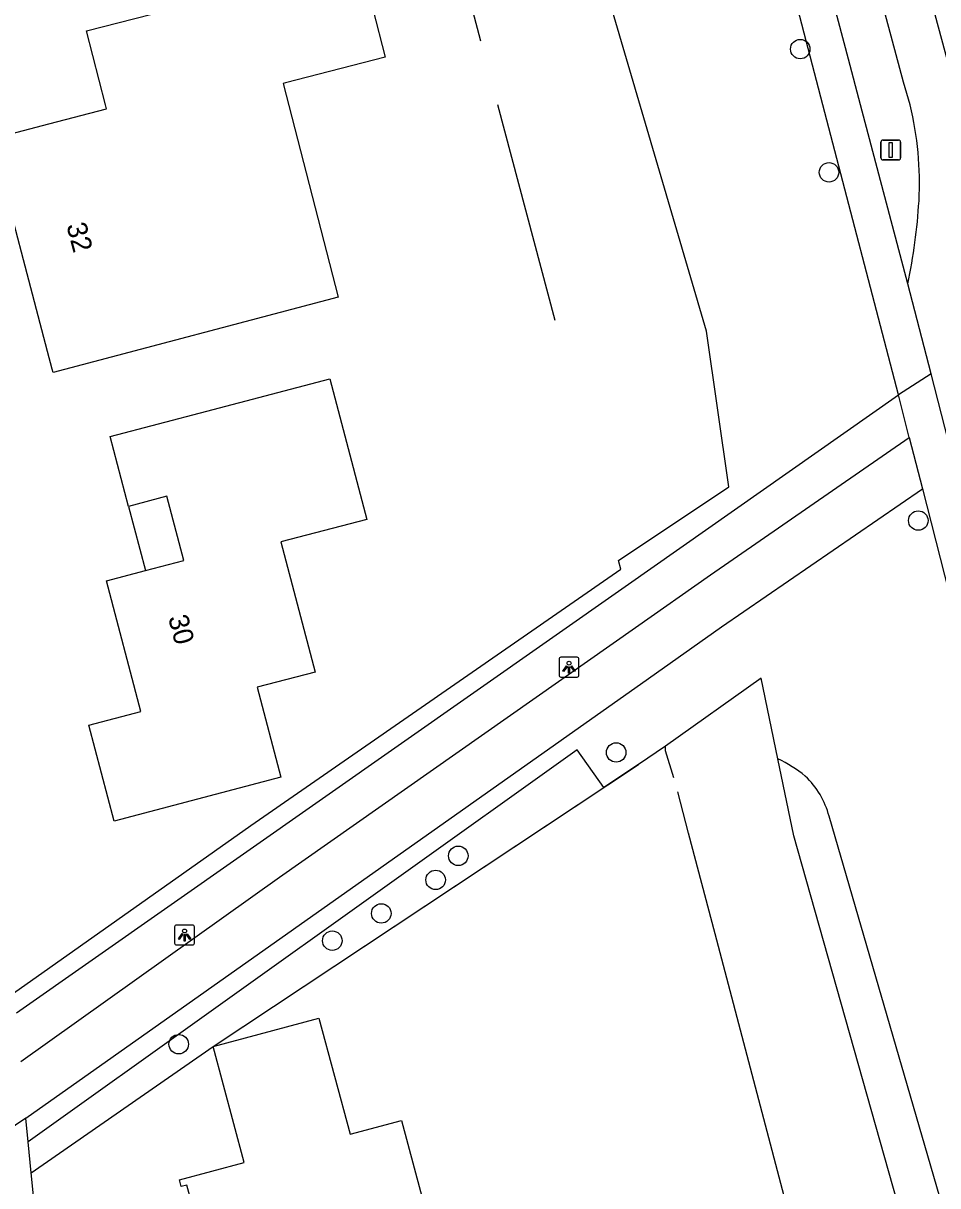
# Model space of a CAD drawing. Extents: x 162157 to 163165, y 378998 to 380775.
# Drawn here: x 162687.3 to 162733.3, y 380445.7 to 380504.1 of the extents above; entities that cross this region are included whole.
import ezdxf

# ---------------------------------------------------------------- set-up
doc = ezdxf.new("R2010")
doc.units = 0
for name, color, linetype in [('IMGEO_Boom', 7, 'Continuous'), ('IMGEO_Fietspad_gesloten', 7, 'Continuous'), ('IMGEO_Fietspad_open', 7, 'Continuous'), ('IMGEO_Gemengd_bos', 7, 'Continuous'), ('IMGEO_Groenvoorziening', 7, 'Continuous'), ('IMGEO_Hek', 7, 'Continuous'), ('IMGEO_Lichtpunt', 7, 'Continuous'), ('IMGEO_Pand', 7, 'Continuous'), ('IMGEO_Pand_nummerreeks', 7, 'Continuous'), ('IMGEO_Pand_overbouw', 7, 'Continuous'), ('IMGEO_Rijbaan_lokaal_onverhard', 7, 'Continuous'), ('IMGEO_Verkeersbordpaal', 7, 'Continuous'), ('IMGEO_Voetpad_open', 7, 'Continuous')]:
    doc.layers.add(name, color=color, linetype=linetype)

msp = doc.modelspace()

# ---------------------------------------------------------------- linework, layer by layer
at = {"layer": 'IMGEO_Boom'}
for centre in [(162726.346, 380502.805), (162727.791, 380496.613), (162732.274, 380479.119), (162717.102, 380467.47), (162709.172, 380462.277), (162708.035, 380461.067), (162705.305, 380459.384), (162702.845, 380458.014), (162695.133, 380452.814)]:
    msp.add_circle(centre, 0.489, dxfattribs=at)
at = {"layer": 'IMGEO_Fietspad_gesloten'}
for points in [[(162731.275, 380485.433), (162727.484, 380500), (162708.817, 380571.718), (162678.5, 380685.887), (162676.539, 380692.528), (162675.802, 380694.61)], [(162731.753, 380491.012), (162729.365, 380500), (162728.763, 380502.292), (162725.914, 380513.099), (162723.595, 380522.008), (162720.624, 380533.396), (162716.618, 380548.723), (162712.249, 380565.205), (162708.349, 380579.63), (162704.901, 380592.927), (162700.995, 380607.612), (162698.81, 380616.109), (162696.091, 380626.224), (162693.684, 380635.214), (162691.566, 380643.43), (162689.217, 380652.338), (162686.635, 380662.341), (162683.661, 380673.381), (162680.65, 380684.701), (162678.313, 380693.64), (162678.104, 380694.353)], [(162732.921, 380486.487), (162731.275, 380485.433)], [(162731.822, 380483.297), (162731.275, 380485.433)], [(162731.822, 380483.297), (162732.486, 380480.708)], [(162732.486, 380480.708), (162737.147, 380462.444), (162744.041, 380435.433), (162753.469, 380399.171), (162793.043, 380252.594), (162793.743, 380250), (162802.348, 380218.82)]]:
    msp.add_lwpolyline(points, dxfattribs=at)
at = {"layer": 'IMGEO_Fietspad_open'}
for points in [[(162687.201, 380451.947), (162700.191, 380461.198), (162718.073, 380473.747), (162721.839, 380476.39), (162731.822, 380483.297)], [(162687.45, 380449.103), (162718.724, 380471.186), (162722.397, 380473.78), (162732.486, 380480.708)], [(162687.45, 380449.103), (162685.825, 380448.011)]]:
    msp.add_lwpolyline(points, dxfattribs=at)
at = {"layer": 'IMGEO_Gemengd_bos'}
for points in [[(162686.842, 380455.383), (162698.747, 380463.798), (162717.329, 380476.675), (162717.214, 380477.109), (162722.756, 380480.815), (162721.635, 380488.635), (162709.746, 380529.126), (162706.597, 380543.52), (162702.968, 380557.567), (162695.09, 380585.37), (162687.837, 380613.552), (162683.878, 380612.514), (162673.502, 380651.377), (162671.402, 380650.811), (162667.467, 380665.693), (162654.457, 380673.698)], [(162725.222, 380467.154), (162724.391, 380471.194), (162719.586, 380467.792), (162718.225, 380466.861), (162716.481, 380465.704)], [(162716.481, 380465.704), (162715.136, 380467.594), (162687.569, 380447.908)], [(162732.512, 380440.284), (162726.017, 380463.29), (162725.222, 380467.154)], [(162794.037, 380217.15), (162795.456, 380217.538), (162786.56, 380250), (162786.126, 380251.585), (162745.395, 380400.219), (162739.025, 380425.583), (162728.963, 380460.227), (162727.791, 380464.262)]]:
    msp.add_lwpolyline(points, dxfattribs=at)
for centre, radius, start, end in [((162721.908, 380460.426), 7.5, 51.32298, 63.77785), ((162723.776, 380463.247), 4.141, 14.18186, 47.1008)]:
    msp.add_arc(centre, radius, start, end, dxfattribs=at)
at = {"layer": 'IMGEO_Groenvoorziening'}
for points in [[(162696.861, 380452.692), (162716.481, 380465.704)], [(162687.725, 380446.347), (162696.861, 380452.692)]]:
    msp.add_lwpolyline(points, dxfattribs=at)
at = {"layer": 'IMGEO_Hek'}
for points in [[(162710.301, 380503.21), (162689.007, 380584.004), (162693.404, 380585.213), (162689.818, 380599.293), (162685.351, 380598.055), (162671.402, 380650.811)], [(162714.03, 380489.167), (162711.154, 380500)], [(162719.577, 380467.545), (162719.586, 380467.792)], [(162720.005, 380466.198), (162719.577, 380467.545)], [(162696.861, 380452.692), (162718.225, 380466.861)], [(162720.737, 380463.414), (162720.19, 380465.495)], [(162778.738, 380250.508), (162768.177, 380283.038), (162722.067, 380458.358), (162720.737, 380463.414)], [(162687.725, 380446.347), (162696.861, 380452.692)]]:
    msp.add_lwpolyline(points, dxfattribs=at)
at = {"layer": 'IMGEO_Lichtpunt'}
for p, q in [((162715.138, 380472.253), (162714.33, 380472.253)), ((162715.138, 380472.253), (162714.33, 380472.253)), ((162714.236, 380472.158), (162714.236, 380471.351)), ((162714.236, 380472.158), (162714.236, 380471.351)), ((162715.232, 380471.351), (162715.232, 380472.158)), ((162715.232, 380471.351), (162715.232, 380472.158)), ((162714.33, 380471.257), (162715.138, 380471.257)), ((162714.33, 380471.257), (162715.138, 380471.257)), ((162694.927, 380458.703), (162694.927, 380457.896)), ((162694.927, 380458.703), (162694.927, 380457.896)), ((162695.829, 380458.798), (162695.021, 380458.798)), ((162695.829, 380458.798), (162695.021, 380458.798)), ((162695.923, 380457.896), (162695.923, 380458.703)), ((162695.923, 380457.896), (162695.923, 380458.703)), ((162695.021, 380457.802), (162695.829, 380457.802)), ((162695.021, 380457.802), (162695.829, 380457.802))]:
    msp.add_line(p, q, dxfattribs=at)
for points in [[(162714.61, 380471.822), (162714.649, 380471.794), (162714.461, 380471.532), (162714.423, 380471.559), (162714.61, 380471.822)], [(162714.712, 380471.774), (162714.759, 380471.774), (162714.759, 380471.452), (162714.712, 380471.452), (162714.712, 380471.774)], [(162714.822, 380471.794), (162714.86, 380471.821), (162715.047, 380471.559), (162715.008, 380471.531), (162714.822, 380471.794)], [(162695.301, 380458.367), (162695.34, 380458.339), (162695.152, 380458.077), (162695.114, 380458.104), (162695.301, 380458.367)], [(162695.403, 380458.319), (162695.45, 380458.319), (162695.45, 380457.997), (162695.403, 380457.997), (162695.403, 380458.319)], [(162695.513, 380458.339), (162695.551, 380458.366), (162695.738, 380458.104), (162695.699, 380458.076), (162695.513, 380458.339)]]:
    msp.add_lwpolyline(points, dxfattribs=at)
for centre in [(162714.735, 380471.956), (162695.426, 380458.501)]:
    msp.add_circle(centre, 0.0994, dxfattribs=at)
for centre, start, end in [((162714.33, 380472.158), 90, 180), ((162714.33, 380472.158), 90, 180), ((162715.138, 380472.158), 0, 90), ((162715.138, 380472.158), 0, 90), ((162714.33, 380471.351), 180, 270), ((162714.33, 380471.351), 180, 270), ((162715.138, 380471.351), 270, 0), ((162715.138, 380471.351), 270, 360), ((162695.021, 380458.703), 90, 180), ((162695.021, 380458.703), 90, 180), ((162695.829, 380458.703), 0, 90), ((162695.829, 380458.703), 0, 90), ((162695.021, 380457.896), 180, 270), ((162695.021, 380457.896), 180, 270), ((162695.829, 380457.896), 270, 0), ((162695.829, 380457.896), 270, 360)]:
    msp.add_arc(centre, 0.0946, start, end, dxfattribs=at)
at = {"layer": 'IMGEO_Pand'}
for points in [[(162704.261, 380507.235), (162705.497, 380502.391), (162700.489, 380501.107), (162700.376, 380501.078), (162703.144, 380490.338), (162688.825, 380486.566), (162688.782, 380486.73), (162688.548, 380487.619), (162685.738, 380498.29), (162688.605, 380499.045), (162691.504, 380499.809), (162691.455, 380500), (162690.505, 380503.727), (162695.35, 380504.963), (162699.252, 380505.958), (162700.5, 380506.276)], [(162702.715, 380486.244), (162703.302, 380484.015), (162704.575, 380479.179), (162700.268, 380478.045), (162701.989, 380471.512), (162699.077, 380470.744), (162700.267, 380466.228), (162691.893, 380464.02), (162690.621, 380468.845), (162693.231, 380469.533), (162691.502, 380476.089), (162693.46, 380476.605), (162695.383, 380477.112), (162694.533, 380480.339), (162692.609, 380479.832), (162691.685, 380483.34), (162696.547, 380484.62), (162702.715, 380486.244)], [(162696.861, 380452.692), (162702.175, 380454.118), (162703.738, 380448.295), (162706.318, 380448.988), (162708.621, 380440.412), (162716.751, 380440.068), (162717.69, 380436.537), (162715.243, 380435.893)], [(162706.789, 380433.67), (162706.058, 380436.437), (162698.3, 380434.356), (162698.195, 380434.749), (162698.934, 380434.947), (162697.232, 380441.287), (162696.774, 380441.164), (162695.547, 380445.737), (162695.259, 380445.659), (162695.169, 380445.994), (162698.424, 380446.868), (162696.861, 380452.692)]]:
    msp.add_lwpolyline(points, dxfattribs=at)
at = {"layer": 'IMGEO_Pand_overbouw'}
msp.add_lwpolyline([(162694.533, 380480.339), (162692.609, 380479.832), (162693.46, 380476.605), (162695.383, 380477.112)], close=True, dxfattribs=at)
at = {"layer": 'IMGEO_Rijbaan_lokaal_onverhard'}
for points in [[(162731.863, 380500), (162731.535, 380501.147), (162730.118, 380506.401), (162727.858, 380514.687), (162725.374, 380523.899), (162721.949, 380536.275), (162719.709, 380544.432), (162717.697, 380551.866), (162715.803, 380559.167), (162709.627, 380583.257), (162699.682, 380620.375), (162691.683, 380650.228), (162687.502, 380663.093), (162687.017, 380664.945), (162684.501, 380673.997), (162682.061, 380682.798), (162679.011, 380694.219), (162678.362, 380695.479)], [(162689.372, 380672.377), (162689.067, 380670.452), (162699.192, 380631.126), (162717.604, 380562.409), (162731.807, 380509.404), (162737.127, 380489.658)], [(162732.921, 380486.487), (162731.753, 380491.012)], [(162734.133, 380481.792), (162732.921, 380486.487)]]:
    msp.add_lwpolyline(points, dxfattribs=at)
for centre, radius, start, end in [((162715.838, 380496.084), 16.497, 356.87322, 13.73228), ((162702.477, 380497.044), 29.891, 348.35816, 356.43276)]:
    msp.add_arc(centre, radius, start, end, dxfattribs=at)
at = {"layer": 'IMGEO_Verkeersbordpaal'}
for p, q in [((162730.394, 380497.336), (162730.394, 380498.136)), ((162730.394, 380498.136), (162730.394, 380497.336)), ((162730.494, 380498.236), (162731.284, 380498.236)), ((162731.284, 380498.236), (162730.494, 380498.236)), ((162731.384, 380498.136), (162731.384, 380497.336)), ((162731.384, 380497.336), (162731.384, 380498.136)), ((162731.284, 380497.236), (162730.494, 380497.236)), ((162730.494, 380497.236), (162731.284, 380497.236))]:
    msp.add_line(p, q, dxfattribs=at)
msp.add_lwpolyline([(162730.814, 380498.111), (162730.964, 380498.111), (162730.964, 380497.361), (162730.814, 380497.361), (162730.814, 380498.111)], dxfattribs=at)
for centre, start, end in [((162730.494, 380498.136), 90, 180), ((162730.494, 380498.136), 90, 180), ((162731.284, 380498.136), 0, 90), ((162731.284, 380498.136), 360, 90), ((162730.494, 380497.336), 180, 270), ((162730.494, 380497.336), 180, 270), ((162731.284, 380497.336), 270, 0), ((162731.284, 380497.336), 270, 0)]:
    msp.add_arc(centre, 0.1, start, end, dxfattribs=at)
at = {"layer": 'IMGEO_Voetpad_open'}
for points in [[(162686.987, 380454.391), (162717.548, 380475.812), (162731.275, 380485.433)], [(162687.569, 380447.908), (162687.45, 380449.103)], [(162687.725, 380446.347), (162687.569, 380447.908)], [(162689.172, 380431.822), (162687.725, 380446.347)]]:
    msp.add_lwpolyline(points, dxfattribs=at)

# ---------------------------------------------------------------- texts
at = {"layer": 'IMGEO_Pand_nummerreeks'}
for s, rotation, p in [('32', 284.75345, (162689.485, 380493.954)), ('30', 284.7741, (162694.593, 380474.25))]:
    msp.add_text(s, height=1, rotation=rotation, dxfattribs=at).set_placement(p)

doc.saveas('drawing.dxf')
